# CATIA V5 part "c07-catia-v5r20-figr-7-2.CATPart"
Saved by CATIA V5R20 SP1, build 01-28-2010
Part number: Part1
Bounding box of the stored display mesh (mm): x -50 to 50, y -75 to 75, z 0 to 10
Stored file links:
  D:\v5_r20\psrt_files_downloaded\c07-catia-v5r20-prt\c07-catia-v5r20-figr-7-2.CATPart
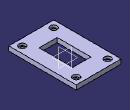
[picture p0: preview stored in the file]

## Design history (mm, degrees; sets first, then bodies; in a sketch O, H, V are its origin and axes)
Body1 (main body)
  Sketch1 on xy-plane, origin (0, 0, 0), H (1, 0, 0), V (0, 1, 0)
    line L1 (-50, 75) -> (50, 75)
    line L2 (50, 75) -> (50, -75)
    line L3 (50, -75) -> (-50, -75)
    line L4 (-50, -75) -> (-50, 75)
    axis line L5 (50, -75) -> (-50, 75)
    length L3 = 100
    length L2 = 150
    horizontal: L1 H, L3 H
    vertical: L2 V, L4 V
    midpoint: O L5
  Pad1: profile Sketch1, direction (0, 0, 1), length 10
  Sketch2 on face of Pad1, origin (0, 0, 10), H (1, 0, 0), V (0, 1, 0)
    line L1 (-20, 37.5) -> (20, 37.5)
    line L2 (20, 37.5) -> (20, -37.5)
    line L3 (20, -37.5) -> (-20, -37.5)
    line L4 (-20, -37.5) -> (-20, 37.5)
    axis line L5 (20, -37.5) -> (-20, 37.5)
    length L3 = 40
    length L2 = 75
    horizontal: L1 H, L3 H
    vertical: L2 V, L4 V
    midpoint: O L5
  Pocket1: profile Sketch2, direction (0, 0, -1), through (limit type 3)
  Sketch3 on face of Pad1, origin (-33.8832, 14.5619, 10), H (1, 0, 0), V (0, 1, 0)
    point P1 (68.8832, -74.5619)
    reference projected line E1 (-16.1168, -89.5619) -> (83.8832, -89.5619) from edge [face of Pad1 | face of Pad1]
    reference projected line E2 (83.8832, -89.5619) -> (83.8832, 60.4381) from edge [face of Pad1 | face of Pad1]
    distance P1 E1 = 15
    distance P1 E2 = 15
  Hole1: placed by Sketch3, at (35, -60, 10) direction (0, 0, -1), diameter 10, through (limit type 3), counterbore diameter 15, counterbore depth 5
  RectPattern1: of Hole1, direction 1 instances 2, spacing 70, along edge [face of Pad1 | face of Pad1] reversed, direction 2 instances 2, spacing 120, along edge [face of Pad1 | face of Pad1]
